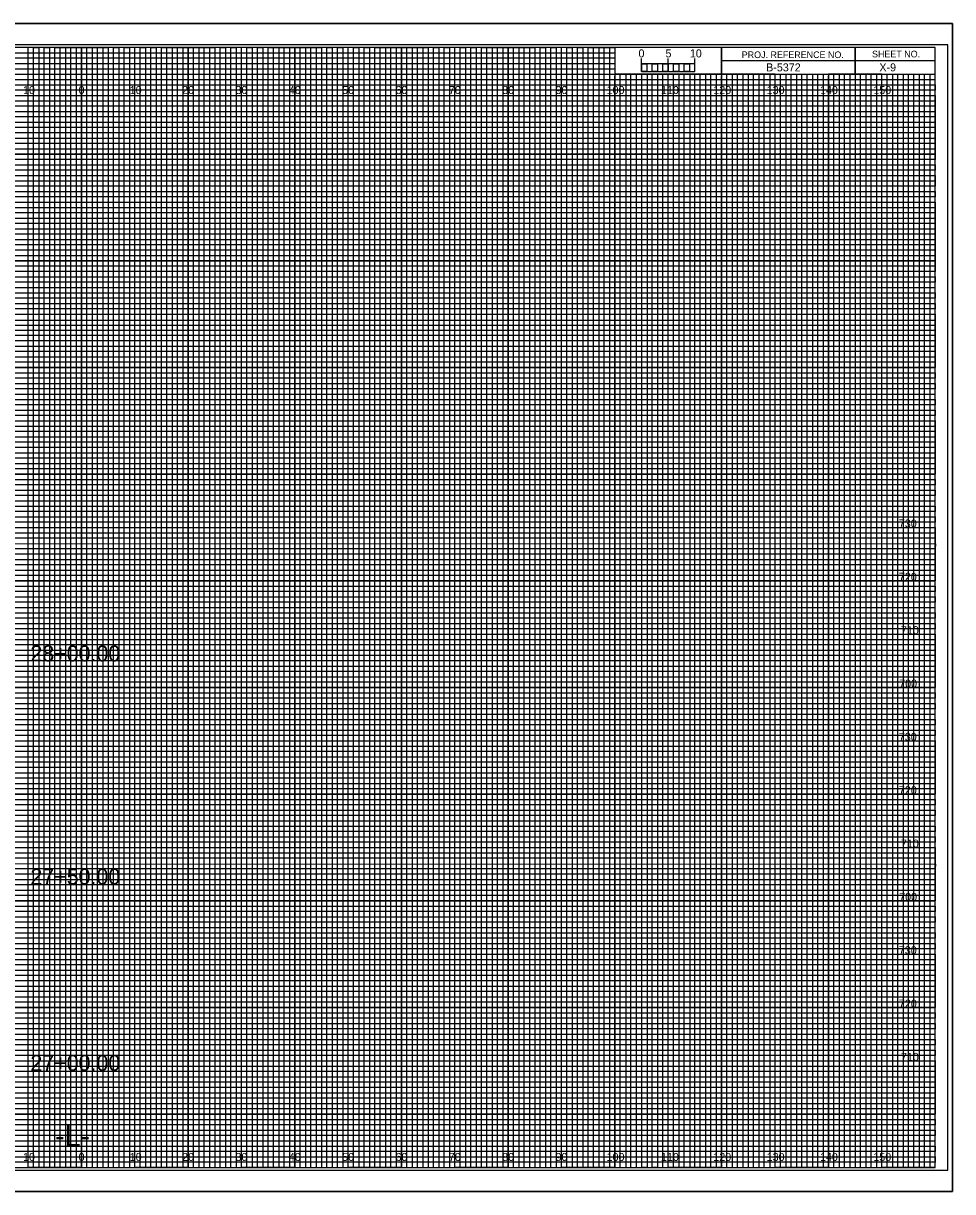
# Model space of a CAD drawing. Extents: x -98 to 717, y -10 to 1974.
# Drawn here: x 149.1 to 323.3, y 1755.5 to 1974.5 of the extents above; entities that cross this region are included whole.
import ezdxf

# ---------------------------------------------------------------- set-up
doc = ezdxf.new("R2010")
doc.units = 0
for name, color, linetype in [('Default', 7, 'Continuous'), ('Exist XS Center Line Elevation Label', 7, 'Continuous'), ('Prop CMT Conc Surface', 7, 'Continuous'), ('Prop CMT Concrete Structures', 7, 'Continuous'), ('Prop CMT Pvmt Course 1', 7, 'Continuous'), ('Prop CMT Pvmt Course 1 CG', 7, 'Continuous'), ('Prop CMT Pvmt Course 2', 7, 'Continuous'), ('Prop CMT Pvmt Course 3', 7, 'Continuous'), ('Prop CMT Pvmt Surface', 7, 'Continuous'), ('Prop CMT Pvmt Surface Shoulder', 7, 'Continuous'), ('Prop CMT Shld Paved Course 1', 7, 'Continuous'), ('Prop CMT Shld Paved Course 2', 7, 'Continuous'), ('Prop CMT Shld Paved Course 3', 7, 'Continuous'), ('Prop CMT Slope Grass', 7, 'Continuous'), ('Prop CMT Subgrade Earthwork', 7, 'Continuous'), ('Prop XS Earthwork Shape', 7, 'Continuous'), ('Prop XS Elevation Labels', 7, 'Continuous'), ('Typical Curb CELL', 7, 'Continuous')]:
    doc.layers.add(name, color=color, linetype=linetype)

msp = doc.modelspace()

# ---------------------------------------------------------------- linework, layer by layer
at = {"layer": 'Default'}
msp.add_lwpolyline([(323.3, 1755.5), (-13.4, 1755.5), (-13.4, 1974.5), (323.3, 1974.5)], close=True, dxfattribs=at)
at = {"layer": 'Exist XS Center Line Elevation Label'}
for p, q in [((0, 1969), (260, 1969)), ((260, 1969), (260, 1967.98)), ((260, 1967.98), (0, 1967.98)), ((0, 1967), (260, 1967)), ((260, 1967), (260, 1965.89)), ((260, 1965.89), (0, 1965.89)), ((0, 1964), (320, 1964))]:
    msp.add_line(p, q, dxfattribs=at)
for points in [[(0, 1963), (270, 1963), (320, 1963), (320, 1962), (0, 1962)], [(0, 1961), (320, 1961), (320, 1959), (0, 1959)], [(0, 1958), (320, 1958), (320, 1957), (0, 1956.98)], [(0, 1956), (320, 1956), (320, 1954), (0, 1954)], [(0, 1953), (320, 1953), (320, 1952), (0, 1952)], [(0, 1951), (320, 1951), (320, 1949), (0, 1949)], [(0, 1948), (320, 1948), (320, 1947), (0, 1947)], [(0, 1946), (320, 1946), (320, 1944), (0, 1944)], [(0, 1943), (320, 1943), (320, 1942), (0, 1942)], [(0, 1941), (320, 1941), (320, 1939), (0, 1939)], [(0, 1938), (320, 1938), (320, 1937), (0, 1937)], [(0, 1936), (320, 1936), (320, 1933.95), (320, 1933), (320, 1932), (0, 1932)], [(0, 1934), (320, 1934), (320, 1933), (0, 1933)], [(0, 1931), (320, 1931), (320, 1929), (0, 1929.03)], [(0, 1929.03), (320, 1929), (320, 1928), (0, 1928)], [(0, 1927), (320, 1927), (320, 1926), (0, 1926)], [(0, 1924), (320, 1924), (320, 1923), (0, 1923)], [(0, 1922), (320, 1922), (320, 1921), (0, 1921)], [(-0.07, 1918.89), (320, 1918.89), (320, 1917.88), (-0.07, 1917.88)], [(0, 1917), (320, 1917), (320, 1916), (0, 1916)], [(0, 1914), (320, 1914), (320, 1913), (0, 1913)], [(0, 1912), (320, 1912), (320, 1911), (0, 1911)], [(0, 1909), (320, 1909), (320, 1908), (0, 1908)], [(0, 1907), (320, 1907), (320, 1906), (0, 1906)], [(0, 1904), (320, 1904), (320, 1903), (0, 1903)], [(0, 1902), (320, 1902), (320, 1901), (0, 1901)], [(0, 1899), (320, 1899), (319.99, 1897.98), (0, 1898)], [(0, 1897), (320, 1897), (320, 1896), (0, 1896)], [(0, 1894), (320, 1894), (320, 1893), (0, 1893)], [(0, 1892), (320, 1892), (320, 1891), (0, 1891)], [(0, 1889), (320, 1889), (320, 1888), (0, 1888)], [(0, 1887), (320, 1887), (320, 1886), (0, 1886)], [(0, 1884), (320, 1884), (320, 1883), (0, 1883)], [(0, 1882), (320, 1882), (320, 1881), (0, 1881)], [(0, 1879), (320, 1879), (320, 1878), (0, 1878)], [(0, 1876.99), (320.07, 1876.91), (320, 1876), (0, 1876)], [(0, 1874), (320, 1874), (320, 1873), (0, 1873)], [(0, 1872), (320, 1872), (320, 1871), (0, 1871)], [(0, 1869), (320, 1869), (320, 1868), (0, 1868)], [(0, 1867), (320, 1867), (320, 1866), (0, 1866)], [(0, 1864), (320, 1864), (320, 1863), (0, 1863)], [(0, 1862), (320, 1862), (320, 1861), (0, 1861)], [(0, 1859), (320, 1859), (320, 1858), (0, 1858)], [(0, 1857), (320, 1857), (320, 1856), (0, 1856)], [(0, 1854), (320, 1854), (320, 1853), (0, 1853)], [(0, 1852), (320, 1852), (320, 1851), (0, 1851)], [(0, 1849), (320, 1849), (320, 1848), (0, 1848)], [(0, 1847), (320, 1847), (320, 1846), (0, 1846)], [(0, 1844), (320, 1844), (320, 1843), (0, 1843)], [(0, 1842), (320, 1842), (320, 1841), (0, 1841)], [(0, 1839), (320, 1839), (319.99, 1837.98), (0, 1838)], [(0, 1837), (320, 1837), (320, 1836), (0, 1836)], [(0, 1834), (320, 1834), (320, 1833), (0, 1833)], [(0, 1832), (320, 1832), (320, 1831), (0, 1831)], [(0, 1829), (320, 1829), (320, 1828), (0, 1828)], [(0, 1827), (320, 1827), (320, 1826), (0, 1826)], [(0, 1824), (320, 1824), (320, 1823), (0, 1823)], [(0, 1822), (320, 1822), (320, 1821), (0, 1821)], [(0, 1819), (320, 1819), (320, 1818), (0, 1818)], [(0, 1816.99), (320.07, 1816.91), (320, 1816), (0, 1816)], [(0, 1814), (320, 1814), (320, 1813), (0, 1813)], [(0, 1812), (320, 1812), (320, 1811), (0, 1811)], [(0, 1809), (320, 1809), (320, 1808), (0, 1808)], [(0, 1807), (320, 1807), (320, 1806), (0, 1806)], [(0, 1804), (320, 1804), (320, 1803), (0, 1803)], [(0, 1802), (320, 1802), (320, 1801), (0, 1801)], [(0, 1799), (320, 1799), (320, 1798), (0, 1798)], [(0, 1797), (320, 1797), (320, 1796), (0, 1796)], [(0, 1794), (320, 1794), (320, 1793), (0, 1793)], [(0, 1792), (320, 1792), (320, 1791), (0, 1791)], [(0, 1789), (320, 1789), (320, 1788), (0, 1788)], [(0, 1787), (320, 1787), (320, 1786), (0, 1786)], [(0, 1784), (320, 1784), (320, 1783), (0, 1783)], [(0, 1782), (320, 1782), (320, 1781), (0, 1781)], [(0, 1779), (320, 1779), (320, 1778), (0, 1778)], [(0, 1777), (320, 1777), (320, 1776), (0, 1776)], [(0, 1774), (320, 1774), (320, 1773), (0, 1773)], [(0, 1772), (320, 1772), (320, 1771), (0, 1771)], [(0, 1769), (320, 1769), (320, 1768), (0, 1768)], [(0, 1767), (320, 1767), (320, 1766), (0, 1766)], [(0, 1764), (320, 1764), (320, 1763), (0, 1763)], [(0, 1762), (320, 1762), (320, 1761), (0, 1761)]]:
    msp.add_lwpolyline(points, dxfattribs=at)
at = {"layer": 'Prop CMT Conc Surface'}
for p, q in [((305, 1970), (305, 1965)), ((305, 1965), (305, 1970)), ((280, 1967.5), (280, 1965)), ((320, 1967.49), (280, 1967.49)), ((280, 1965), (320, 1965))]:
    msp.add_line(p, q, dxfattribs=at)
for points in [[(320, 1970), (0, 1970), (0, 1760), (320, 1760)], [(280, 1970), (260, 1970), (260, 1965.03), (280, 1965.03)], [(320, 1970), (280, 1970), (280, 1965), (320, 1965)]]:
    msp.add_lwpolyline(points, close=True, dxfattribs=at)
at = {"layer": 'Prop CMT Concrete Structures'}
for p, q in [((150, 1760), (150, 1970)), ((160, 1760), (160, 1970)), ((170, 1760), (170, 1970)), ((180, 1760), (180, 1970)), ((190, 1760), (190, 1970)), ((200, 1760), (200, 1970)), ((210, 1760), (210, 1970)), ((220, 1760), (220, 1970)), ((230, 1760), (230, 1970)), ((240, 1760), (240, 1970)), ((250, 1760), (250, 1970)), ((260, 1760), (260, 1964.69)), ((270, 1760), (270, 1964.69)), ((280, 1760), (280, 1964.69)), ((290, 1760), (290, 1964.69)), ((300, 1760), (300, 1964.69)), ((310, 1760), (310, 1964.69)), ((0, 1960), (320, 1960)), ((0, 1950), (320, 1950)), ((0, 1940), (320, 1940)), ((0, 1930), (320, 1930)), ((0, 1920), (320, 1920)), ((0, 1910), (320, 1910)), ((0, 1900), (320, 1900)), ((0, 1890), (320, 1890)), ((0, 1880), (320, 1880)), ((0, 1870), (320, 1870)), ((0, 1860), (320, 1860)), ((0, 1850), (320, 1850)), ((0, 1840), (320, 1840)), ((0, 1830), (320, 1830)), ((0, 1820), (320, 1820)), ((0, 1810), (320, 1810)), ((0, 1800), (320, 1800)), ((0, 1790), (320, 1790)), ((0, 1780), (320, 1780)), ((0, 1770), (320, 1770))]:
    msp.add_line(p, q, dxfattribs=at)
at = {"layer": 'Prop CMT Pvmt Course 2'}
msp.add_lwpolyline([(-13.4, 1755.5), (323.3, 1755.5), (323.3, 1974.5), (-13.4, 1974.5)], close=True, dxfattribs=at)
at = {"layer": 'Prop CMT Pvmt Course 3'}
msp.add_lwpolyline([(-10.8, 1759.5), (322.4, 1759.5), (322.4, 1970.5), (-10.8, 1970.5)], close=True, dxfattribs=at)
at = {"layer": 'Prop CMT Pvmt Surface'}
for p, q in [((323.3, 1974.5), (-13.4, 1974.5)), ((-13.4, 1755.5), (323.3, 1755.5))]:
    msp.add_line(p, q, dxfattribs=at)
at = {"layer": 'Prop CMT Slope Grass'}
for p, q in [((265, 1965.49), (265, 1967.9)), ((265, 1966.9), (265, 1967.9)), ((270, 1965.49), (270, 1967.9)), ((275, 1965.49), (275, 1967.9)), ((275, 1966.9), (275, 1967.9))]:
    msp.add_line(p, q, dxfattribs=at)
for points in [[(275, 1966.9), (265, 1966.9), (265, 1965.49), (275, 1965.49)], [(265, 1966.9), (266, 1966.9), (266, 1965.49), (265, 1965.49)], [(267, 1966.9), (268, 1966.9), (268, 1965.49), (267, 1965.49)], [(269, 1966.9), (270, 1966.9), (270, 1965.49), (269, 1965.49)], [(271, 1966.9), (272, 1966.9), (272, 1965.49), (271, 1965.49)], [(273, 1966.9), (274, 1966.9), (274, 1965.49), (273, 1965.49)]]:
    msp.add_lwpolyline(points, close=True, dxfattribs=at)
at = {"layer": 'Prop CMT Subgrade Earthwork'}
for p, q in [((267, 1965), (266.01, 1965)), ((266.01, 1965), (266.01, 1760)), ((267, 1760), (267, 1965)), ((269, 1965), (268, 1965)), ((268, 1965), (268, 1760)), ((269, 1760), (269, 1965)), ((266.01, 1760), (265, 1760)), ((268, 1760), (267, 1760))]:
    msp.add_line(p, q, dxfattribs=at)
for points in [[(150, 1760), (151, 1760), (151, 1970), (152, 1970), (152, 1760)], [(152, 1760), (153, 1760), (153, 1970), (154, 1970), (154, 1760)], [(155, 1760), (156, 1760), (156, 1970), (157, 1970), (157, 1760)], [(157, 1760), (158, 1760), (158, 1970), (159, 1970), (159, 1760)], [(160, 1760), (161, 1760), (161, 1970), (162, 1970), (162, 1760)], [(162, 1760), (163, 1760), (163, 1970), (164, 1970), (164, 1760)], [(165, 1760), (166, 1760), (166, 1970), (167, 1970), (167, 1760)], [(167, 1760), (168, 1760), (168, 1970), (169, 1970), (169, 1760)], [(170, 1760), (171, 1760), (171, 1970), (172, 1970), (172, 1760)], [(172, 1760), (173, 1760), (173, 1970), (174, 1970), (174, 1760)], [(175, 1760), (176, 1760), (176, 1970), (177, 1970), (177, 1760)], [(177, 1760), (178, 1760), (178, 1970), (179, 1970), (179, 1760)], [(180, 1760), (181, 1760), (181, 1970), (182, 1970), (182, 1760)], [(182, 1760), (183, 1760), (183, 1970), (184, 1970), (184, 1760)], [(185, 1760), (186, 1760), (186, 1970), (187, 1970), (187, 1760)], [(187, 1760), (188, 1760), (188, 1970), (189, 1970), (189, 1760)], [(190, 1760), (191, 1760), (191, 1970), (192, 1970), (192, 1760)], [(192, 1760), (193, 1760), (193, 1970), (194, 1970), (194, 1760)], [(195, 1760), (196, 1760), (196, 1970), (197, 1970), (197, 1760)], [(197, 1760), (198, 1760), (198, 1970), (199, 1970), (199, 1760)], [(200, 1760), (201, 1760), (201, 1970), (202, 1970), (202, 1760)], [(202, 1760), (203, 1760), (203, 1970), (204, 1970), (204, 1760)], [(205, 1760), (206, 1760), (206, 1970), (207, 1970), (207, 1760)], [(207, 1760), (208, 1760), (208, 1970), (209, 1970), (209, 1760)], [(210, 1760), (211, 1760), (211, 1970), (212, 1970), (212, 1760)], [(212, 1760), (213, 1760), (213, 1970), (214, 1970), (214, 1760)], [(215, 1760), (216, 1760), (216, 1970), (217, 1970), (217, 1760)], [(217, 1760), (218, 1760), (218, 1970), (219, 1970), (219, 1760)], [(220, 1760), (221, 1760), (221, 1970), (222, 1970), (222, 1760)], [(222, 1760), (223, 1760), (223, 1970), (224, 1970), (224, 1760)], [(225, 1760), (226, 1760), (226, 1970), (227, 1970), (227, 1760)], [(227, 1760), (228, 1760), (228, 1970), (229, 1970), (229, 1760)], [(230, 1760), (231, 1760), (231, 1970), (232, 1970), (232, 1760)], [(232, 1760), (233, 1760), (233, 1970), (234, 1970), (234, 1760)], [(235, 1760), (236, 1760), (236, 1970), (237, 1970), (237, 1760)], [(237, 1760), (238, 1760), (238, 1970), (239, 1970), (239, 1760)], [(240, 1760), (241, 1760), (241, 1970), (242, 1970), (242, 1760)], [(242, 1760), (243, 1760), (243, 1970), (244, 1970), (244, 1760)], [(245, 1760), (246, 1760), (246, 1970), (247, 1970), (247, 1760)], [(247, 1760), (248, 1760), (248, 1970), (249, 1970), (249, 1760)], [(250, 1760), (251, 1760), (251, 1970), (252, 1970), (252, 1760)], [(252, 1760), (253, 1760), (253, 1970), (254, 1970), (254, 1760)], [(255, 1760), (256, 1760), (256, 1970), (257, 1970), (257, 1760)], [(257, 1760), (258, 1760), (258, 1970), (259, 1970), (259, 1760)], [(260, 1760), (261, 1760), (261, 1965), (262.02, 1965), (262.02, 1760)], [(262, 1760), (263, 1760), (263, 1965), (263.99, 1965), (263.99, 1760)], [(270, 1760), (270.98, 1760), (270.98, 1965), (272, 1965), (272, 1760)], [(272, 1760), (273, 1760), (273, 1965), (274.05, 1965), (274.05, 1760)], [(275, 1760), (276, 1760), (276, 1965), (277, 1965), (277, 1760)], [(277, 1760), (278, 1760), (278, 1965), (279, 1965), (279, 1760)], [(280, 1760), (281, 1760), (281, 1965), (282, 1965), (282, 1760)], [(282, 1760), (283, 1760), (283, 1965), (284, 1965), (284, 1760)], [(285, 1760), (286, 1760), (286, 1965), (287, 1965), (287, 1760)], [(287, 1760), (288, 1760), (288, 1965), (289, 1965), (289, 1760)], [(290, 1760), (291, 1760), (291, 1965), (292, 1965), (292, 1760)], [(292, 1760), (293, 1760), (293, 1965), (294, 1965), (294, 1760)], [(295, 1760), (296, 1760), (296, 1965), (297, 1965), (297, 1760)], [(297, 1760), (298, 1760), (298, 1965), (299, 1965), (299, 1760)], [(300, 1760), (301, 1760), (301, 1965), (302, 1965), (302, 1760)], [(302, 1760), (303, 1760), (303, 1965), (304, 1965), (304, 1760)], [(305, 1760), (306, 1760), (306, 1965), (307, 1965), (307, 1760)], [(307, 1760), (308, 1760), (308, 1965), (309, 1965), (309, 1760)], [(310, 1760), (311, 1760), (311, 1965), (312, 1965), (312, 1760)], [(312, 1760), (313, 1760), (313, 1965), (314, 1965), (314, 1760)], [(315, 1760), (316, 1760), (316, 1965), (317, 1965), (317, 1760)], [(317, 1760), (318, 1760), (318, 1965), (319, 1965), (319, 1760)]]:
    msp.add_lwpolyline(points, dxfattribs=at)
at = {"layer": 'Prop XS Elevation Labels'}
for p, q in [((150, 1970), (140, 1970)), ((150, 1760), (150, 1970)), ((170, 1970), (160, 1970)), ((160, 1970), (160, 1760)), ((170, 1760), (170, 1970)), ((190, 1970), (180, 1970)), ((180, 1970), (180, 1760)), ((190, 1760), (190, 1970)), ((210, 1970), (200, 1970)), ((200, 1970), (200, 1760)), ((210, 1760), (210, 1970)), ((230, 1970), (220, 1970)), ((220, 1970), (220, 1760)), ((230, 1760), (230, 1970)), ((250, 1970), (240, 1970)), ((240, 1970), (240, 1760)), ((250, 1760), (250, 1970)), ((260, 1970), (260, 1760)), ((270, 1760), (270, 1965)), ((290, 1965), (280, 1965)), ((280, 1965), (280, 1760)), ((290, 1760), (290, 1965)), ((310, 1965), (300, 1965)), ((300, 1965), (300, 1760)), ((310, 1760), (310, 1965)), ((160, 1760), (150, 1760)), ((180, 1760), (170, 1760)), ((200, 1760), (190, 1760)), ((220, 1760), (210, 1760)), ((240, 1760), (230, 1760)), ((260, 1760), (250, 1760)), ((280, 1760), (270, 1760)), ((300, 1760), (290, 1760)), ((320, 1760), (310, 1760)), ((320, 1760), (320, 1760))]:
    msp.add_line(p, q, dxfattribs=at)
for points in [[(0, 1960), (320, 1960), (320, 1950), (0, 1950)], [(0, 1940), (320, 1940), (320, 1930), (0, 1930)], [(0, 1920), (320, 1920), (320, 1910), (0, 1910)], [(0, 1900), (320, 1900), (320, 1890), (0, 1890)], [(0, 1880), (320, 1880), (320, 1870), (0, 1870)], [(0, 1860), (320, 1860), (320, 1850), (0, 1850)], [(0, 1840), (320, 1840), (320, 1830), (0, 1830)], [(0, 1820), (320, 1820), (320, 1810), (0, 1810)], [(0, 1800), (320, 1800), (320, 1790), (0, 1790)], [(0, 1780), (320, 1780), (320, 1770), (0, 1770)]]:
    msp.add_lwpolyline(points, dxfattribs=at)
at = {"layer": 'Typical Curb CELL'}
for points in [[(145, 1760), (155, 1760), (155, 1970), (165, 1970), (165, 1760), (175, 1760), (175, 1970), (185, 1970), (185, 1760), (195, 1760), (195, 1970), (205, 1970), (205, 1760), (215, 1760), (215, 1970), (225, 1970), (225, 1760), (235, 1760), (235, 1970), (245, 1970), (245, 1760), (255, 1760), (255, 1970), (259.93, 1970), (260, 1970), (260, 1965), (264.99, 1965), (264.99, 1760), (275, 1760), (275, 1965), (285, 1965), (285, 1760), (295, 1760), (295, 1965), (305, 1965), (305, 1760), (315, 1760), (315, 1965)], [(0, 1965), (275, 1965)], [(0, 1945), (320, 1945), (320, 1955), (0, 1955)], [(0, 1925), (320, 1925), (320, 1935), (0, 1935)], [(0, 1905), (320, 1905), (320, 1915), (0, 1915)], [(0, 1885), (320, 1885), (320, 1895), (0, 1895)], [(0, 1865), (320, 1865), (320, 1875), (0, 1875)], [(0, 1845), (320, 1845), (320, 1855), (0, 1855)], [(0, 1825), (320, 1825), (320, 1835), (0, 1835)], [(0, 1805), (320, 1805), (320, 1815), (0, 1815)], [(0, 1785), (320, 1785), (320, 1795), (0, 1795)], [(0, 1765), (320, 1765), (320, 1775), (0, 1775)]]:
    msp.add_lwpolyline(points, dxfattribs=at)

# ---------------------------------------------------------------- texts
at = {"layer": 'Prop CMT Conc Surface'}
for s, p in [('PROJ. REFERENCE NO.', (283.77, 1967.99)), ('SHEET NO.', (308.19, 1968.12))]:
    msp.add_text(s, height=1.25, dxfattribs=at).set_placement(p)
at = {"layer": 'Prop CMT Pvmt Course 1'}
for s, p in [('28+00.00', (150.41, 1854.89)), ('27+50.00', (150.41, 1813.06)), ('27+00.00', (150.41, 1778.13))]:
    msp.add_text(s, height=3, dxfattribs=at).set_placement(p)
at = {"layer": 'Prop CMT Pvmt Course 1 CG'}
for s, p in [('730', (313.22, 1880)), ('720', (313.23, 1870)), ('710', (313.61, 1860)), ('700', (313.28, 1850)), ('730', (313.22, 1840)), ('720', (313.23, 1830)), ('710', (313.61, 1820)), ('700', (313.28, 1810)), ('730', (313.22, 1800)), ('720', (313.23, 1790)), ('710', (313.61, 1780))]:
    msp.add_text(s, height=1.5, dxfattribs=at).set_placement(p)
at = {"layer": 'Prop CMT Pvmt Surface Shoulder'}
for s, p in [('5', (269.47, 1968.12)), ('10', (274.04, 1968.12))]:
    msp.add_text(s, height=1.5, dxfattribs=at).set_placement(p)
at = {"layer": 'Prop CMT Shld Paved Course 1'}
msp.add_text('X-9', height=1.5, dxfattribs=at).set_placement((309.57, 1965.5))
at = {"layer": 'Prop CMT Shld Paved Course 2'}
msp.add_text('B-5372', height=1.5, dxfattribs=at).set_placement((288.34, 1965.5))
at = {"layer": 'Prop CMT Shld Paved Course 3'}
msp.add_text('-L-', height=4, dxfattribs=at).set_placement((155.06, 1764))
at = {"layer": 'Prop CMT Slope Grass'}
msp.add_text('0', height=1.5, dxfattribs=at).set_placement((264.41, 1968.12))
at = {"layer": 'Prop XS Earthwork Shape'}
for s, p in [('10', (149.04, 1961.25)), ('0', (159.45, 1961.25)), ('0', (159.45, 1961.25)), ('10', (169.04, 1961.25)), ('20', (178.86, 1961.25)), ('30', (188.86, 1961.25)), ('40', (198.86, 1961.25)), ('50', (208.86, 1961.25)), ('60', (218.86, 1961.25)), ('70', (228.86, 1961.25)), ('80', (238.86, 1961.25)), ('90', (248.86, 1961.25)), ('100', (258.44, 1961.25)), ('110', (268.62, 1961.25)), ('120', (278.44, 1961.25)), ('130', (288.44, 1961.25)), ('140', (298.44, 1961.25)), ('150', (308.44, 1961.25)), ('10', (149.04, 1761.25)), ('0', (159.45, 1761.25)), ('0', (159.45, 1761.25)), ('10', (169.04, 1761.25)), ('20', (178.86, 1761.25)), ('30', (188.86, 1761.25)), ('40', (198.86, 1761.25)), ('50', (208.86, 1761.25)), ('60', (218.86, 1761.25)), ('70', (228.86, 1761.25)), ('80', (238.86, 1761.25)), ('90', (248.86, 1761.25)), ('100', (258.44, 1761.25)), ('110', (268.62, 1761.25)), ('120', (278.44, 1761.25)), ('130', (288.44, 1761.25)), ('140', (298.44, 1761.25)), ('150', (308.44, 1761.25))]:
    msp.add_text(s, height=1.5, dxfattribs=at).set_placement(p)

doc.saveas('drawing.dxf')
